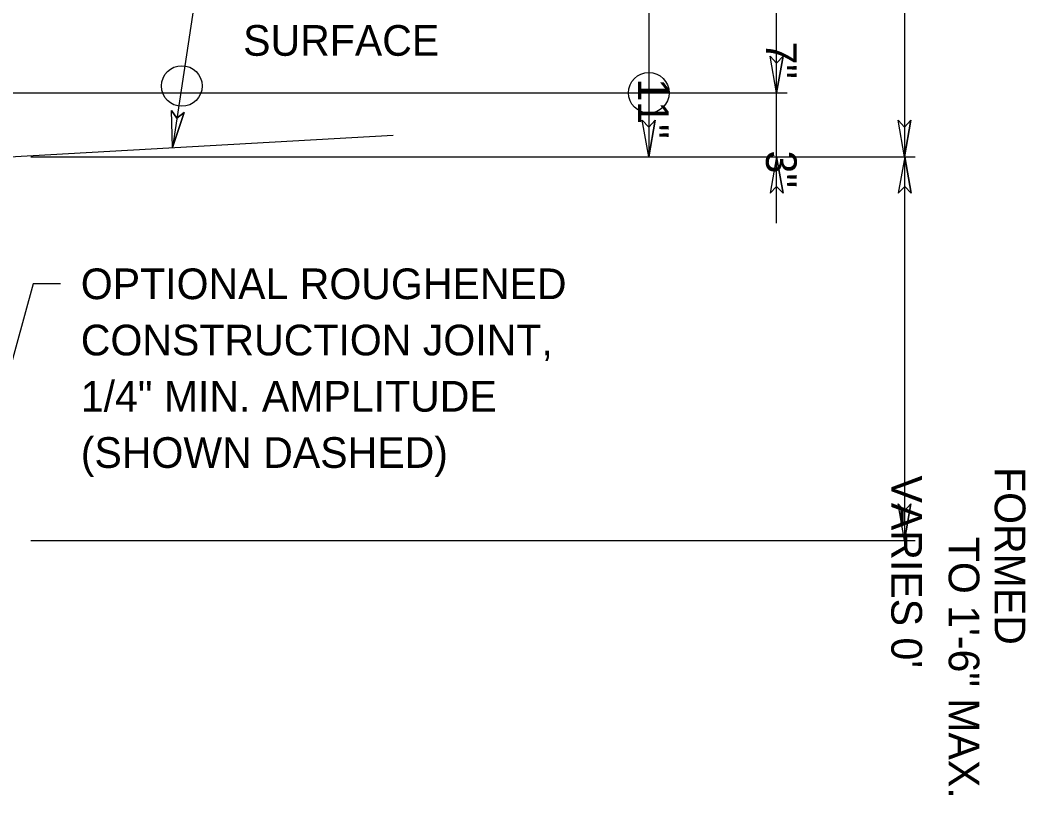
# Model space of a CAD drawing. Extents: x -26.46 to -19.21, y -3.62 to 6.25.
# Drawn here: x -22.178 to -20.211, y 2.166 to 3.682 of the extents above; entities that cross this region are included whole.
import ezdxf

# ---------------------------------------------------------------- set-up
doc = ezdxf.new("R2010")
doc.units = 0
for name, color, linetype in [('ANNO-WOUT', 7, 'Continuous'), ('DETL-DIMS', 7, 'Continuous'), ('Level 10', 7, 'Continuous'), ('Level 12', 7, 'Continuous'), ('SECT-GRND_P', 7, 'Continuous')]:
    doc.layers.add(name, color=color, linetype=linetype)

msp = doc.modelspace()

# ---------------------------------------------------------------- linework, layer by layer
at = {"layer": 'ANNO-WOUT'}
for centre in [(-21.8618, 3.5529), (-20.9488, 3.5396)]:
    msp.add_circle(centre, 0.0397, dxfattribs=at)
at = {"layer": 'DETL-DIMS'}
for p, q in [((-20.6988, 3.5396), (-20.7115, 3.6111)), ((-20.6988, 3.5976), (-20.7115, 3.6111)), ((-20.6988, 3.5396), (-20.6863, 3.6111)), ((-20.6863, 3.6111), (-20.6988, 3.5976)), ((-21.8801, 3.4324), (-21.8819, 3.505)), ((-21.8714, 3.4898), (-21.8819, 3.505)), ((-21.8801, 3.4324), (-21.857, 3.5012)), ((-21.857, 3.5012), (-21.8714, 3.4898)), ((-20.9488, 3.4146), (-20.9615, 3.4861)), ((-20.9488, 3.4726), (-20.9615, 3.4861)), ((-20.9488, 3.4146), (-20.9363, 3.4861)), ((-20.9363, 3.4861), (-20.9488, 3.4726)), ((-20.4488, 3.4146), (-20.4615, 3.4861)), ((-20.4488, 3.4726), (-20.4615, 3.4861)), ((-20.4488, 3.4146), (-20.4363, 3.4861)), ((-20.4363, 3.4861), (-20.4488, 3.4726)), ((-20.6988, 3.4146), (-20.7115, 3.3431)), ((-20.6988, 3.4146), (-20.6863, 3.3431)), ((-20.4484, 3.4146), (-20.4611, 3.3431)), ((-20.4484, 3.4146), (-20.4359, 3.3431)), ((-20.6988, 3.3566), (-20.7115, 3.3431)), ((-20.6863, 3.3431), (-20.6988, 3.3566)), ((-20.4484, 3.3566), (-20.4611, 3.3431)), ((-20.4359, 3.3431), (-20.4484, 3.3566)), ((-20.4488, 2.6642), (-20.4615, 2.7357)), ((-20.4488, 2.7222), (-20.4615, 2.7357)), ((-20.4488, 2.6642), (-20.4363, 2.7357)), ((-20.4363, 2.7357), (-20.4488, 2.7222))]:
    msp.add_line(p, q, dxfattribs=at)
for points in [[(-20.6863, 3.6111), (-20.6988, 3.5396), (-20.7115, 3.6111), (-20.6988, 3.5976)], [(-21.857, 3.5012), (-21.8801, 3.4324), (-21.8819, 3.505), (-21.8714, 3.4898)], [(-20.9363, 3.4861), (-20.9488, 3.4146), (-20.9615, 3.4861), (-20.9488, 3.4726)], [(-20.4363, 3.4861), (-20.4488, 3.4146), (-20.4615, 3.4861), (-20.4488, 3.4726)], [(-20.6863, 3.3431), (-20.6988, 3.4146), (-20.7115, 3.3431), (-20.6988, 3.3566)], [(-20.4359, 3.3431), (-20.4484, 3.4146), (-20.4611, 3.3431), (-20.4484, 3.3566)], [(-20.4363, 2.7357), (-20.4488, 2.6642), (-20.4615, 2.7357), (-20.4488, 2.7222)]]:
    msp.add_lwpolyline(points, close=True, dxfattribs=at)
at = {"layer": 'Level 10'}
for p, q in [((-20.4488, 5.1646), (-20.4488, 3.4146)), ((-20.9488, 3.8729), (-20.9488, 3.4146)), ((-20.6988, 3.5396), (-20.6988, 3.8327)), ((-21.8298, 3.7639), (-21.8801, 3.4324)), ((-22.4072, 3.5396), (-20.678, 3.5396)), ((-20.6988, 3.2849), (-20.6988, 3.5396)), ((-22.1572, 3.4146), (-20.428, 3.4146)), ((-20.4488, 3.4146), (-20.4488, 2.6642)), ((-22.1526, 3.166), (-22.2901, 2.6648)), ((-22.0987, 3.166), (-22.1526, 3.166)), ((-22.1572, 2.6642), (-20.428, 2.6642))]:
    msp.add_line(p, q, dxfattribs=at)
at = {"layer": 'SECT-GRND_P'}
msp.add_line((-22.1988, 3.4146), (-21.4484, 3.4565), dxfattribs=at)

# ---------------------------------------------------------------- texts
at = {"layer": 'Level 12'}
for s, p in [('SURFACE', (-21.7419, 3.612)), ('OPTIONAL ROUGHENED ', (-22.0593, 3.136)), ('CONSTRUCTION JOINT, ', (-22.0593, 3.026)), ('1/4" MIN. AMPLITUDE ', (-22.0593, 2.916)), ('(SHOWN DASHED)', (-22.0593, 2.806))]:
    msp.add_text(s, height=0.06001, dxfattribs=at).set_placement(p)
for s, p in [('7"', (-20.7196, 3.64)), ('11"', (-20.9696, 3.5676)), ('3"', (-20.7196, 3.4266)), ('FORMED', (-20.2724, 2.8076)), ("VARIES 0'", (-20.4746, 2.791)), ('TO 1\'-6" MAX.', (-20.3624, 2.6711))]:
    msp.add_text(s, height=0.06001, rotation=270, dxfattribs=at).set_placement(p)

doc.saveas('drawing.dxf')
